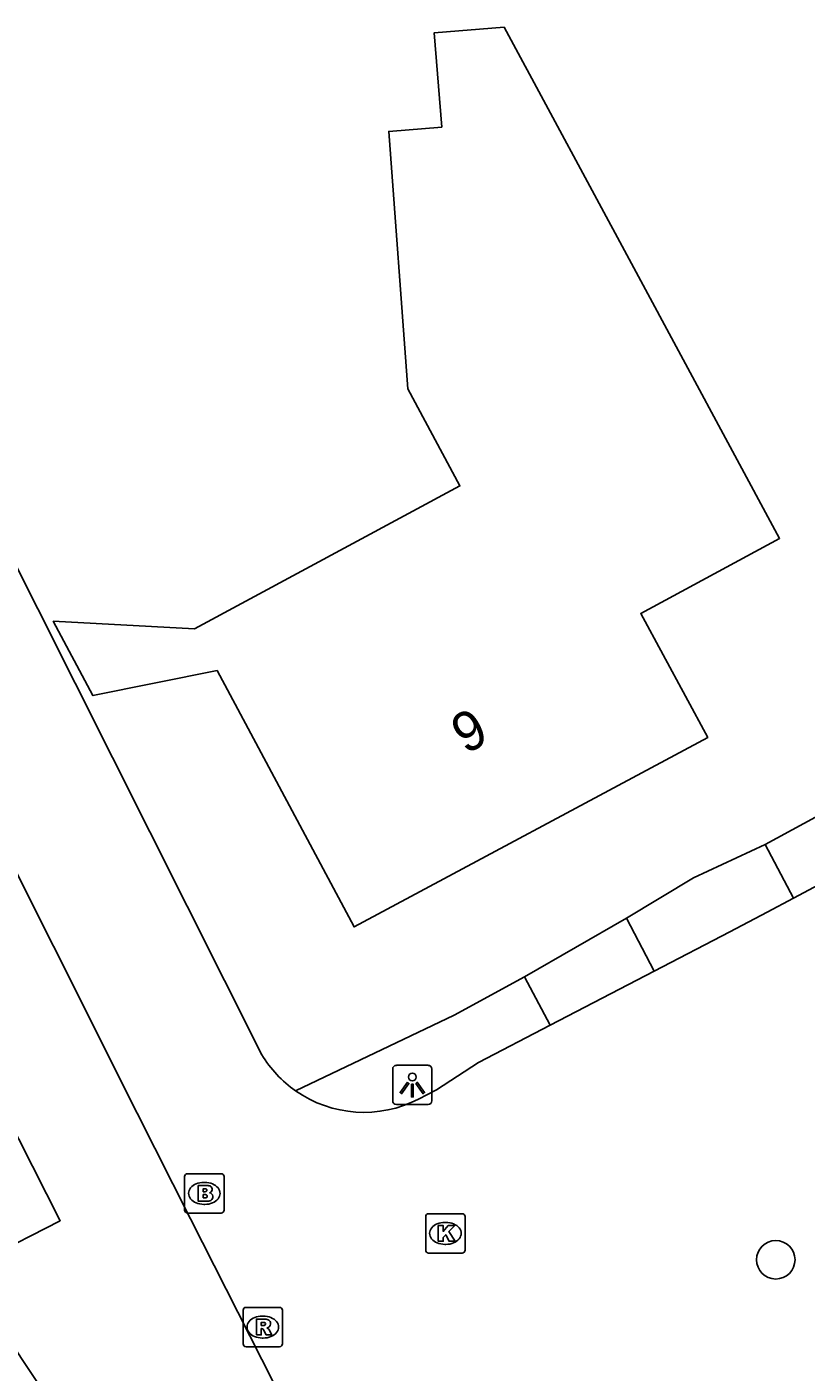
# Model space of a CAD drawing. Extents: x 157321 to 158827, y 386650 to 388532.
# Drawn here: x 158190.6 to 158210.41, y 387182.26 to 387216.45 of the extents above; entities that cross this region are included whole.
import ezdxf

# ---------------------------------------------------------------- set-up
doc = ezdxf.new("R2010")
doc.units = 0
for name, color, linetype in [('IMGEO_Boom', 7, 'Continuous'), ('IMGEO_Brandkraan', 7, 'Continuous'), ('IMGEO_Groenvoorziening', 7, 'Continuous'), ('IMGEO_Kolk', 7, 'Continuous'), ('IMGEO_Lichtpunt', 7, 'Continuous'), ('IMGEO_Pand', 7, 'Continuous'), ('IMGEO_Pand_nummerreeks', 7, 'Continuous'), ('IMGEO_Parkeervlak_open', 7, 'Continuous'), ('IMGEO_Rioolput', 7, 'Continuous'), ('IMGEO_Voetpad_open', 7, 'Continuous')]:
    doc.layers.add(name, color=color, linetype=linetype)

msp = doc.modelspace()

# ---------------------------------------------------------------- linework, layer by layer
at = {"layer": 'IMGEO_Boom'}
msp.add_circle((158209.637, 387185.118), 0.489, dxfattribs=at)
at = {"layer": 'IMGEO_Brandkraan'}
for p, q in [((158194.683, 387187.306), (158195.535, 387187.306)), ((158194.608, 387186.38), (158194.608, 387187.232)), ((158195.096, 387187.086), (158195.121, 387187.086)), ((158195.609, 387187.232), (158195.609, 387186.38)), ((158195.535, 387186.306), (158194.683, 387186.306)), ((158195.119, 387186.526), (158195.094, 387186.526))]:
    msp.add_line(p, q, dxfattribs=at)
for points in [[(158194.683, 387187.306), (158195.535, 387187.306)], [(158194.608, 387186.38), (158194.608, 387187.232)], [(158194.956, 387187.006), (158194.956, 387186.606), (158195.169, 387186.606)], [(158195.187, 387187.006), (158194.956, 387187.006)], [(158195.609, 387187.232), (158195.609, 387186.38)], [(158195.135, 387186.925), (158195.081, 387186.925), (158195.081, 387186.849)], [(158195.081, 387186.849), (158195.134, 387186.849)], [(158195.143, 387186.773), (158195.081, 387186.773), (158195.081, 387186.692)], [(158195.081, 387186.692), (158195.143, 387186.692)], [(158195.535, 387186.306), (158194.683, 387186.306)]]:
    msp.add_lwpolyline(points, dxfattribs=at)
for centre, radius, start, end in [((158194.685, 387187.23), 0.0765, 91.552, 178.448), ((158194.685, 387187.23), 0.0765, 91.552, 178.448), ((158195.533, 387187.23), 0.0765, 1.552, 88.448), ((158195.533, 387187.23), 0.0765, 1.552, 88.448), ((158195.191, 387186.861), 0.145, 59.4692, 91.5367), ((158195.216, 387186.908), 0.0922, 285.5137, 58.1501), ((158195.136, 387186.887), 0.0379, 267.8285, 90.9355), ((158195.144, 387186.732), 0.0404, 269.8759, 90.5077), ((158195.175, 387186.857), 0.251, 268.6676, 293.5347), ((158195.221, 387186.716), 0.105, 301.3115, 78.989), ((158194.685, 387186.382), 0.0765, 181.552, 268.448), ((158194.685, 387186.382), 0.0765, 181.552, 268.448), ((158195.533, 387186.382), 0.0765, 271.552, 358.448), ((158195.533, 387186.382), 0.0765, 271.552, 358.448)]:
    msp.add_arc(centre, radius, start, end, dxfattribs=at)
for centre, major_axis, ratio, start_param, end_param in [((158195.095, 387186.806), (-0.387, 0.002), 0.722429, 4.712389, 7.853982), ((158195.12, 387186.806), (-0.39, 0.002), 0.717154, 1.570796, 4.712389)]:
    msp.add_ellipse(centre, major_axis=major_axis, ratio=ratio, start_param=start_param, end_param=end_param, dxfattribs=at)
at = {"layer": 'IMGEO_Groenvoorziening'}
for points in [[(158205.838, 387193.797), (158207.549, 387194.826), (158209.369, 387195.668)], [(158197.427, 387189.413), (158201.462, 387191.335), (158203.245, 387192.312)]]:
    msp.add_lwpolyline(points, dxfattribs=at)
at = {"layer": 'IMGEO_Kolk'}
for p, q in [((158200.812, 387186.289), (158201.664, 387186.289)), ((158200.737, 387185.363), (158200.737, 387186.215)), ((158201.225, 387186.069), (158201.25, 387186.069)), ((158201.738, 387186.215), (158201.738, 387185.363)), ((158201.664, 387185.289), (158200.812, 387185.289)), ((158201.248, 387185.509), (158201.223, 387185.509))]:
    msp.add_line(p, q, dxfattribs=at)
for points in [[(158200.812, 387186.289), (158201.664, 387186.289)], [(158200.737, 387185.363), (158200.737, 387186.215)], [(158201.058, 387185.989), (158201.181, 387185.989), (158201.181, 387185.838), (158201.311, 387185.989), (158201.475, 387185.989), (158201.329, 387185.838), (158201.482, 387185.589), (158201.33, 387185.589), (158201.245, 387185.753), (158201.181, 387185.686), (158201.181, 387185.589), (158201.058, 387185.589), (158201.058, 387185.989)], [(158201.738, 387186.215), (158201.738, 387185.363)], [(158201.664, 387185.289), (158200.812, 387185.289)]]:
    msp.add_lwpolyline(points, dxfattribs=at)
for centre, start, end in [((158200.814, 387186.213), 91.552, 178.448), ((158200.814, 387186.213), 91.552, 178.448), ((158201.662, 387186.213), 1.552, 88.448), ((158201.662, 387186.213), 1.552, 88.448), ((158200.814, 387185.365), 181.552, 268.448), ((158200.814, 387185.365), 181.552, 268.448), ((158201.662, 387185.365), 271.552, 358.448), ((158201.662, 387185.365), 271.552, 358.448)]:
    msp.add_arc(centre, 0.0765, start, end, dxfattribs=at)
for centre, major_axis, ratio, start_param, end_param in [((158201.224, 387185.789), (-0.387, 0.002), 0.722429, 4.712389, 7.853982), ((158201.249, 387185.789), (-0.39, 0.002), 0.717154, 1.570796, 4.712389)]:
    msp.add_ellipse(centre, major_axis=major_axis, ratio=ratio, start_param=start_param, end_param=end_param, dxfattribs=at)
at = {"layer": 'IMGEO_Lichtpunt'}
for p, q in [((158200.8, 387190.06), (158199.992, 387190.06)), ((158200.8, 387190.06), (158199.992, 387190.06)), ((158199.898, 387189.965), (158199.898, 387189.158)), ((158199.898, 387189.965), (158199.898, 387189.158)), ((158200.894, 387189.158), (158200.894, 387189.965)), ((158200.894, 387189.158), (158200.894, 387189.965)), ((158199.992, 387189.064), (158200.8, 387189.064)), ((158199.992, 387189.064), (158200.8, 387189.064))]:
    msp.add_line(p, q, dxfattribs=at)
for points in [[(158200.272, 387189.629), (158200.311, 387189.601), (158200.123, 387189.339), (158200.085, 387189.366), (158200.272, 387189.629)], [(158200.374, 387189.581), (158200.421, 387189.581), (158200.421, 387189.259), (158200.374, 387189.259), (158200.374, 387189.581)], [(158200.484, 387189.601), (158200.522, 387189.628), (158200.709, 387189.366), (158200.67, 387189.338), (158200.484, 387189.601)]]:
    msp.add_lwpolyline(points, dxfattribs=at)
msp.add_circle((158200.397, 387189.763), 0.0994, dxfattribs=at)
for centre, start, end in [((158199.992, 387189.965), 90, 180), ((158199.992, 387189.965), 90, 180), ((158200.8, 387189.965), 0, 90), ((158200.8, 387189.965), 0, 90), ((158199.992, 387189.158), 180, 270), ((158199.992, 387189.158), 180, 270), ((158200.8, 387189.158), 270, 0), ((158200.8, 387189.158), 270, 360)]:
    msp.add_arc(centre, 0.0946, start, end, dxfattribs=at)
at = {"layer": 'IMGEO_Pand'}
for points in [[(158206.027, 387210.325), (158202.729, 387216.441), (158200.951, 387216.298), (158201.143, 387213.902), (158199.797, 387213.794), (158200.28, 387207.252), (158201.605, 387204.785), (158194.863, 387201.153), (158191.267, 387201.345), (158192.278, 387199.456), (158195.432, 387200.09), (158198.916, 387193.579), (158207.908, 387198.392), (158206.205, 387201.546), (158209.735, 387203.45), (158206.027, 387210.325)], [(158178.524, 387186.149), (158176.322, 387190.638), (158179.847, 387192.398), (158179.547, 387192.866), (158183.49, 387195.479), (158184.978, 387193.274), (158187.23, 387194.407), (158191.447, 387186.111), (158189.583, 387185.163), (158188.965, 387184.849), (158193.64, 387177.822), (158194.214, 387178.203), (158195, 387177.021), (158190.851, 387174.232), (158188.72, 387172.8), (158181.916, 387182.662), (158180.559, 387181.999), (158178.524, 387186.149)]]:
    msp.add_lwpolyline(points, dxfattribs=at)
at = {"layer": 'IMGEO_Parkeervlak_open'}
for points in [[(158196.57, 387190.328), (158184.22, 387214.881), (158184.356, 387216.458)], [(158180.674, 387214.601), (158180.644, 387214.276), (158193.399, 387188.847), (158194.761, 387186.161), (158201.391, 387173.082), (158225.64, 387178.479)], [(158210.087, 387194.305), (158209.415, 387193.956), (158208.473, 387193.451), (158206.543, 387192.449)], [(158203.902, 387191.078), (158202.077, 387190.131), (158201.011, 387189.441), (158200.558, 387189.201)]]:
    msp.add_lwpolyline(points, dxfattribs=at)
for centre, radius, start, end in [((158199.178, 387191.912), 3.051, 211.2689, 234.9817), ((158199.168, 387191.9), 3.035, 235.0009, 297.2519)]:
    msp.add_arc(centre, radius, start, end, dxfattribs=at)
at = {"layer": 'IMGEO_Rioolput'}
for p, q in [((158196.169, 387183.909), (158197.021, 387183.909)), ((158196.094, 387182.983), (158196.094, 387183.835)), ((158196.582, 387183.689), (158196.607, 387183.689)), ((158197.095, 387183.835), (158197.095, 387182.983)), ((158197.021, 387182.909), (158196.169, 387182.909)), ((158196.605, 387183.129), (158196.58, 387183.129))]:
    msp.add_line(p, q, dxfattribs=at)
for points in [[(158196.169, 387183.909), (158197.021, 387183.909)], [(158196.094, 387182.983), (158196.094, 387183.835)], [(158196.683, 387183.607), (158196.431, 387183.609), (158196.431, 387183.209)], [(158197.095, 387183.835), (158197.095, 387182.983)], [(158196.431, 387183.209), (158196.555, 387183.209), (158196.555, 387183.371), (158196.566, 387183.371)], [(158196.609, 387183.528), (158196.555, 387183.528), (158196.555, 387183.447)], [(158196.555, 387183.447), (158196.607, 387183.447)], [(158196.613, 387183.342), (158196.684, 387183.209), (158196.824, 387183.209), (158196.759, 387183.335)], [(158197.021, 387182.909), (158196.169, 387182.909)]]:
    msp.add_lwpolyline(points, dxfattribs=at)
for centre, radius, start, end in [((158196.171, 387183.833), 0.0765, 91.552, 178.448), ((158196.171, 387183.833), 0.0765, 91.552, 178.448), ((158197.019, 387183.833), 0.0765, 1.552, 88.448), ((158197.019, 387183.833), 0.0765, 1.552, 88.448), ((158196.682, 387183.497), 0.109, 350.3612, 89.416), ((158196.565, 387183.318), 0.0533, 26.0293, 88.6989), ((158196.591, 387183.636), 0.19, 274.7715, 282.9687), ((158196.615, 387183.432), 0.0964, 77.0061, 93.1865), ((158196.629, 387183.489), 0.0378, 276.6634, 79.6772), ((158196.68, 387183.497), 0.112, 277.5842, 350.9817), ((158196.664, 387183.282), 0.108, 29.5134, 73.7905), ((158196.171, 387182.985), 0.0765, 181.552, 268.448), ((158196.171, 387182.985), 0.0765, 181.552, 268.448), ((158197.019, 387182.985), 0.0765, 271.552, 358.448), ((158197.019, 387182.985), 0.0765, 271.552, 358.448)]:
    msp.add_arc(centre, radius, start, end, dxfattribs=at)
for centre, major_axis, ratio, start_param, end_param in [((158196.581, 387183.409), (-0.387, 0.002), 0.722429, 4.712389, 7.853982), ((158196.606, 387183.409), (-0.39, 0.002), 0.717154, 1.570796, 4.712389)]:
    msp.add_ellipse(centre, major_axis=major_axis, ratio=ratio, start_param=start_param, end_param=end_param, dxfattribs=at)
at = {"layer": 'IMGEO_Voetpad_open'}
for points in [[(158213.782, 387198.067), (158209.369, 387195.668)], [(158214.526, 387196.669), (158210.087, 387194.305)], [(158209.369, 387195.668), (158210.087, 387194.305)], [(158203.245, 387192.312), (158205.838, 387193.797)], [(158206.543, 387192.449), (158205.838, 387193.797)], [(158206.543, 387192.449), (158203.902, 387191.078)], [(158203.902, 387191.078), (158203.245, 387192.312)]]:
    msp.add_lwpolyline(points, dxfattribs=at)

# ---------------------------------------------------------------- texts
at = {"layer": 'IMGEO_Pand_nummerreeks'}
msp.add_text('9', height=1, rotation=28.1551, dxfattribs=at).set_placement((158201.746, 387197.952))

doc.saveas('drawing.dxf')
